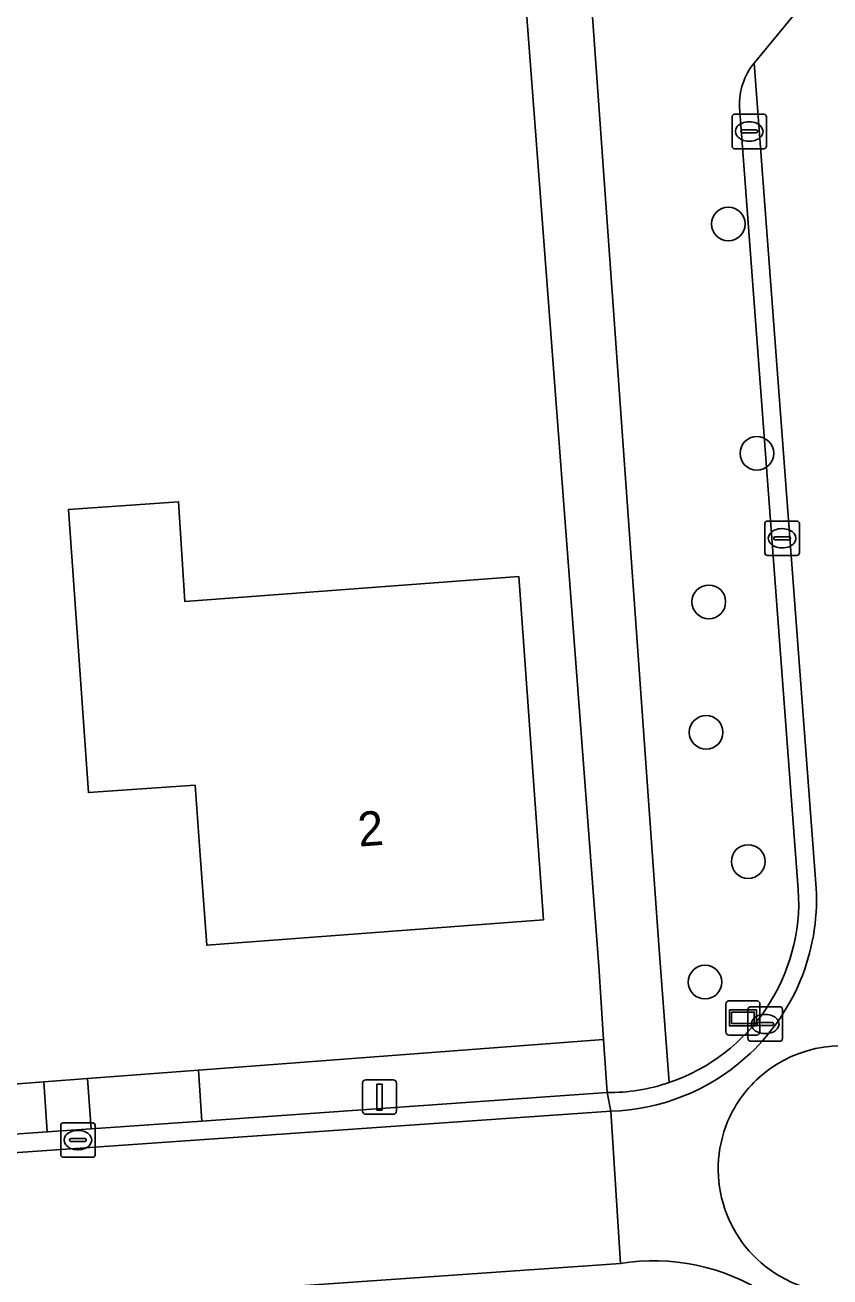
# Model space of a CAD drawing. Extents: x 162661 to 163484, y 380247 to 381230.
# Drawn here: x 163109.5 to 163132.86, y 380399.85 to 380436.19 of the extents above; entities that cross this region are included whole.
import ezdxf

# ---------------------------------------------------------------- set-up
doc = ezdxf.new("R2010")
doc.units = 0
for name, color, linetype in [('IMGEO_Boom', 7, 'Continuous'), ('IMGEO_Erf', 7, 'Continuous'), ('IMGEO_Groenvoorziening', 7, 'Continuous'), ('IMGEO_Kolk', 7, 'Continuous'), ('IMGEO_Lichtmast', 7, 'Continuous'), ('IMGEO_Pand', 7, 'Continuous'), ('IMGEO_Pand_nummerreeks', 7, 'Continuous'), ('IMGEO_Rijbaan_lokaal_gesloten', 7, 'Continuous'), ('IMGEO_Rijbaan_lokaal_open', 7, 'Continuous'), ('IMGEO_Straatnaambord', 7, 'Continuous'), ('IMGEO_Voetpad_open', 7, 'Continuous')]:
    doc.layers.add(name, color=color, linetype=linetype)

msp = doc.modelspace()

# ---------------------------------------------------------------- linework, layer by layer
at = {"layer": 'IMGEO_Boom'}
for centre in [(163129.913, 380430.416), (163130.742, 380423.759), (163129.347, 380419.447), (163129.269, 380415.66), (163130.49, 380411.91), (163129.236, 380408.411)]:
    msp.add_circle(centre, 0.489, dxfattribs=at)
at = {"layer": 'IMGEO_Erf'}
msp.add_lwpolyline([(163059.202, 380401.669), (163072.831, 380402.7), (163076.355, 380402.967), (163083.412, 380403.501), (163085.079, 380403.627), (163089.515, 380403.963), (163093.438, 380404.26), (163106.644, 380405.259), (163110.041, 380405.516), (163111.313, 380405.612), (163114.53, 380405.856), (163126.293, 380406.746), (163126.155, 380408.871), (163123.094, 380449.195)], dxfattribs=at)
msp.add_lwpolyline([(163110.764, 380422.13), (163113.956, 380422.354), (163114.136, 380419.459), (163123.829, 380420.187), (163124.544, 380410.218), (163114.776, 380409.483), (163114.583, 380412.095), (163114.433, 380414.127), (163111.341, 380413.91)], close=True, dxfattribs=at)
at = {"layer": 'IMGEO_Groenvoorziening'}
for points in [[(163129.483, 380443.709), (163128.717, 380454.219), (163128.599, 380455.668), (163127.675, 380455.574), (163127.354, 380455.539), (163124.446, 380455.354), (163125.156, 380447.82), (163127.91, 380409.357), (163128.192, 380405.494)], [(163130.659, 380435.085), (163132.068, 380436.79)], [(163131.945, 380411.096), (163130.236, 380433.81)]]:
    msp.add_lwpolyline(points, dxfattribs=at)
for points in [[(163126.293, 380406.746), (163114.53, 380405.856), (163114.634, 380404.378), (163126.393, 380405.204)], [(163111.313, 380405.612), (163110.041, 380405.516), (163110.143, 380404.063), (163111.415, 380404.152)]]:
    msp.add_lwpolyline(points, close=True, dxfattribs=at)
for centre, radius, start, end in [((163132.167, 380433.877), 1.932, 141.3069, 181.9851), ((163126.42, 380410.739), 5.536, 288.6626, 3.698)]:
    msp.add_arc(centre, radius, start, end, dxfattribs=at)
at = {"layer": 'IMGEO_Kolk'}
for p, q in [((163130.02, 380432.675), (163130.02, 380433.527)), ((163130.095, 380433.601), (163130.947, 380433.601)), ((163130.508, 380433.381), (163130.533, 380433.381)), ((163131.021, 380433.527), (163131.021, 380432.675)), ((163130.279, 380433.095), (163130.279, 380433.107)), ((163130.717, 380433.058), (163130.319, 380433.058)), ((163130.322, 380433.144), (163130.72, 380433.144)), ((163130.763, 380433.107), (163130.763, 380433.095)), ((163130.947, 380432.601), (163130.095, 380432.601)), ((163130.531, 380432.821), (163130.506, 380432.821)), ((163130.974, 380420.867), (163130.974, 380421.719)), ((163131.049, 380421.793), (163131.901, 380421.793)), ((163131.975, 380421.719), (163131.975, 380420.867)), ((163131.276, 380421.336), (163131.674, 380421.336)), ((163131.462, 380421.573), (163131.487, 380421.573)), ((163131.233, 380421.287), (163131.233, 380421.299)), ((163131.671, 380421.25), (163131.273, 380421.25)), ((163131.485, 380421.013), (163131.46, 380421.013)), ((163131.717, 380421.299), (163131.717, 380421.287)), ((163131.901, 380420.793), (163131.049, 380420.793)), ((163130.484, 380406.769), (163130.484, 380407.621)), ((163130.559, 380407.695), (163131.411, 380407.695)), ((163131.485, 380407.621), (163131.485, 380406.769)), ((163130.743, 380407.189), (163130.743, 380407.201)), ((163130.786, 380407.238), (163131.184, 380407.238)), ((163130.972, 380407.475), (163130.997, 380407.475)), ((163131.227, 380407.201), (163131.227, 380407.189)), ((163131.181, 380407.152), (163130.783, 380407.152)), ((163130.995, 380406.915), (163130.97, 380406.915)), ((163131.411, 380406.695), (163130.559, 380406.695)), ((163110.534, 380403.4), (163110.534, 380404.252)), ((163110.609, 380404.326), (163111.461, 380404.326)), ((163111.535, 380404.252), (163111.535, 380403.4)), ((163111.022, 380404.106), (163111.047, 380404.106)), ((163110.793, 380403.82), (163110.793, 380403.832)), ((163111.231, 380403.783), (163110.833, 380403.783)), ((163110.836, 380403.869), (163111.234, 380403.869)), ((163111.045, 380403.546), (163111.02, 380403.546)), ((163111.277, 380403.832), (163111.277, 380403.82)), ((163111.461, 380403.326), (163110.609, 380403.326))]:
    msp.add_line(p, q, dxfattribs=at)
for points in [[(163130.02, 380432.675), (163130.02, 380433.527)], [(163130.095, 380433.601), (163130.947, 380433.601)], [(163131.021, 380433.527), (163131.021, 380432.675)], [(163130.947, 380432.601), (163130.095, 380432.601)], [(163130.974, 380420.867), (163130.974, 380421.719)], [(163131.049, 380421.793), (163131.901, 380421.793)], [(163131.975, 380421.719), (163131.975, 380420.867)], [(163131.901, 380420.793), (163131.049, 380420.793)], [(163130.484, 380406.769), (163130.484, 380407.621)], [(163130.559, 380407.695), (163131.411, 380407.695)], [(163131.485, 380407.621), (163131.485, 380406.769)], [(163131.411, 380406.695), (163130.559, 380406.695)], [(163110.534, 380403.4), (163110.534, 380404.252)], [(163110.609, 380404.326), (163111.461, 380404.326)], [(163111.535, 380404.252), (163111.535, 380403.4)], [(163111.461, 380403.326), (163110.609, 380403.326)]]:
    msp.add_lwpolyline(points, dxfattribs=at)
for centre, radius, start, end in [((163130.097, 380433.525), 0.0765, 91.552, 178.448), ((163130.097, 380433.525), 0.0765, 91.552, 178.448), ((163130.945, 380433.525), 0.0765, 1.552, 88.448), ((163130.945, 380433.525), 0.0765, 1.552, 88.448), ((163130.319, 380433.104), 0.0403, 85.8775, 175.7526), ((163130.316, 380433.094), 0.0366, 178.938, 274.7102), ((163130.72, 380433.101), 0.043, 264.8664, 352.4533), ((163130.724, 380433.106), 0.0386, 1.7309, 96.639), ((163130.097, 380432.677), 0.0765, 181.552, 268.448), ((163130.097, 380432.677), 0.0765, 181.552, 268.448), ((163130.945, 380432.677), 0.0765, 271.552, 358.448), ((163130.945, 380432.677), 0.0765, 271.552, 358.448), ((163131.051, 380421.717), 0.0765, 91.552, 178.448), ((163131.051, 380421.717), 0.0765, 91.552, 178.448), ((163131.899, 380421.717), 0.0765, 1.552, 88.448), ((163131.899, 380421.717), 0.0765, 1.552, 88.448), ((163131.273, 380421.296), 0.0403, 85.8775, 175.7526), ((163131.678, 380421.298), 0.0386, 1.7309, 96.639), ((163131.27, 380421.286), 0.0366, 178.938, 274.7102), ((163131.674, 380421.293), 0.043, 264.8664, 352.4533), ((163131.051, 380420.869), 0.0765, 181.552, 268.448), ((163131.051, 380420.869), 0.0765, 181.552, 268.448), ((163131.899, 380420.869), 0.0765, 271.552, 358.448), ((163131.899, 380420.869), 0.0765, 271.552, 358.448), ((163130.561, 380407.619), 0.0765, 91.552, 178.448), ((163130.561, 380407.619), 0.0765, 91.552, 178.448), ((163131.409, 380407.619), 0.0765, 1.552, 88.448), ((163131.409, 380407.619), 0.0765, 1.552, 88.448), ((163130.783, 380407.198), 0.0403, 85.8775, 175.7526), ((163130.78, 380407.188), 0.0366, 178.938, 274.7102), ((163131.184, 380407.195), 0.043, 264.8664, 352.4533), ((163131.188, 380407.2), 0.0386, 1.7309, 96.639), ((163130.561, 380406.771), 0.0765, 181.552, 268.448), ((163130.561, 380406.771), 0.0765, 181.552, 268.448), ((163131.409, 380406.771), 0.0765, 271.552, 358.448), ((163131.409, 380406.771), 0.0765, 271.552, 358.448), ((163110.611, 380404.25), 0.0765, 91.552, 178.448), ((163110.611, 380404.25), 0.0765, 91.552, 178.448), ((163111.459, 380404.25), 0.0765, 1.552, 88.448), ((163111.459, 380404.25), 0.0765, 1.552, 88.448), ((163110.833, 380403.829), 0.0403, 85.8775, 175.7526), ((163110.83, 380403.819), 0.0366, 178.938, 274.7102), ((163111.234, 380403.826), 0.043, 264.8664, 352.4533), ((163111.238, 380403.831), 0.0386, 1.7309, 96.639), ((163110.611, 380403.402), 0.0765, 181.552, 268.448), ((163110.611, 380403.402), 0.0765, 181.552, 268.448), ((163111.459, 380403.402), 0.0765, 271.552, 358.448), ((163111.459, 380403.402), 0.0765, 271.552, 358.448)]:
    msp.add_arc(centre, radius, start, end, dxfattribs=at)
for centre, major_axis, ratio, start_param, end_param in [((163130.507, 380433.101), (-0.387, 0.002), 0.722429, 4.712389, 7.853982), ((163130.532, 380433.101), (-0.39, 0.002), 0.717154, 1.570796, 4.712389), ((163131.461, 380421.293), (-0.387, 0.002), 0.722429, 4.712389, 7.853982), ((163131.486, 380421.293), (-0.39, 0.002), 0.717154, 1.570796, 4.712389), ((163130.971, 380407.195), (-0.387, 0.002), 0.722429, 4.712389, 7.853982), ((163130.996, 380407.195), (-0.39, 0.002), 0.717154, 1.570796, 4.712389), ((163111.021, 380403.826), (-0.387, 0.002), 0.722429, 4.712389, 7.853982), ((163111.046, 380403.826), (-0.39, 0.002), 0.717154, 1.570796, 4.712389)]:
    msp.add_ellipse(centre, major_axis=major_axis, ratio=ratio, start_param=start_param, end_param=end_param, dxfattribs=at)
at = {"layer": 'IMGEO_Lichtmast'}
for p, q in [((163119.293, 380404.673), (163119.293, 380405.473)), ((163119.293, 380405.473), (163119.293, 380404.673)), ((163119.393, 380405.573), (163120.183, 380405.573)), ((163120.183, 380405.573), (163119.393, 380405.573)), ((163120.283, 380405.473), (163120.283, 380404.673)), ((163120.283, 380404.673), (163120.283, 380405.473)), ((163120.183, 380404.573), (163119.393, 380404.573)), ((163119.393, 380404.573), (163120.183, 380404.573))]:
    msp.add_line(p, q, dxfattribs=at)
msp.add_lwpolyline([(163119.713, 380405.448), (163119.863, 380405.448), (163119.863, 380404.698), (163119.713, 380404.698), (163119.713, 380405.448)], dxfattribs=at)
for centre, start, end in [((163119.393, 380405.473), 90, 180), ((163119.393, 380405.473), 90, 180), ((163120.183, 380405.473), 0, 90), ((163120.183, 380405.473), 360, 90), ((163119.393, 380404.673), 180, 270), ((163119.393, 380404.673), 180, 270), ((163120.183, 380404.673), 270, 0), ((163120.183, 380404.673), 270, 0)]:
    msp.add_arc(centre, 0.1, start, end, dxfattribs=at)
at = {"layer": 'IMGEO_Pand'}
msp.add_lwpolyline([(163111.341, 380413.91), (163114.433, 380414.127), (163114.583, 380412.095), (163114.776, 380409.483), (163124.544, 380410.218), (163123.829, 380420.187), (163114.136, 380419.459), (163113.956, 380422.354), (163110.764, 380422.13)], close=True, dxfattribs=at)
at = {"layer": 'IMGEO_Rijbaan_lokaal_gesloten'}
for points in [[(163132.068, 380436.79), (163130.659, 380435.085), (163132.464, 380411.134)], [(163126.503, 380404.662), (163062.407, 380400.199)], [(163064.883, 380395.926), (163126.779, 380400.24), (163126.503, 380404.662)], [(163126.503, 380404.662), (163126.779, 380400.24)]]:
    msp.add_lwpolyline(points, dxfattribs=at)
for centre, radius, start, end in [((163126.323, 380410.81), 6.149, 311.713, 3.0175), ((163133.212, 380402.964), 3.601, 2.865, 130.302), ((163126.318, 380410.816), 6.156, 271.7174, 311.7136), ((163133.207, 380402.967), 3.595, 130.2765, 156.7899), ((163133.223, 380402.987), 3.602, 157.1843, 239.7923), ((163133.224, 380402.985), 3.601, 239.7745, 328.8373), ((163127.761, 380394.35), 5.972, 56.8255, 99.4679)]:
    msp.add_arc(centre, radius, start, end, dxfattribs=at)
at = {"layer": 'IMGEO_Rijbaan_lokaal_open'}
for points in [[(163132.464, 380411.134), (163130.659, 380435.085)], [(163130.236, 380433.81), (163131.945, 380411.096)], [(163126.503, 380404.662), (163126.393, 380405.204), (163114.634, 380404.378), (163111.415, 380404.152), (163110.143, 380404.063), (163106.745, 380403.824), (163093.564, 380402.898), (163089.584, 380402.619), (163085.196, 380402.311), (163083.53, 380402.194), (163076.444, 380401.696), (163072.919, 380401.448), (163062.309, 380400.703)], [(163126.393, 380405.204), (163126.503, 380404.662)], [(163062.407, 380400.199), (163126.503, 380404.662)], [(163126.779, 380400.24), (163064.883, 380395.926)]]:
    msp.add_lwpolyline(points, dxfattribs=at)
for centre, radius, start, end in [((163132.167, 380433.877), 1.932, 141.3069, 181.9851), ((163126.42, 380410.739), 5.536, 288.6626, 3.698), ((163126.323, 380410.81), 6.149, 311.713, 3.0175), ((163133.212, 380402.964), 3.601, 2.865, 130.302), ((163126.318, 380410.816), 6.156, 271.7174, 311.7136), ((163133.207, 380402.967), 3.595, 130.2765, 156.7899), ((163126.43, 380410.701), 5.497, 269.6166, 288.698), ((163133.223, 380402.987), 3.602, 157.1843, 239.7923), ((163133.224, 380402.985), 3.601, 239.7745, 328.8373), ((163127.761, 380394.35), 5.972, 56.8255, 99.4679)]:
    msp.add_arc(centre, radius, start, end, dxfattribs=at)
at = {"layer": 'IMGEO_Straatnaambord'}
for p, q in [((163129.842, 380406.972), (163129.842, 380407.772)), ((163129.842, 380407.772), (163129.842, 380406.972)), ((163129.942, 380407.872), (163130.732, 380407.872)), ((163130.732, 380407.872), (163129.942, 380407.872)), ((163130.832, 380407.772), (163130.832, 380406.972)), ((163130.832, 380406.972), (163130.832, 380407.772)), ((163130.732, 380406.872), (163129.942, 380406.872)), ((163129.942, 380406.872), (163130.732, 380406.872))]:
    msp.add_line(p, q, dxfattribs=at)
for points in [[(163129.943, 380407.604), (163130.731, 380407.604), (163130.731, 380407.14), (163129.943, 380407.14), (163129.943, 380407.604)], [(163130.008, 380407.539), (163130.008, 380407.205), (163130.666, 380407.205), (163130.666, 380407.539), (163130.008, 380407.539)]]:
    msp.add_lwpolyline(points, dxfattribs=at)
for centre, start, end in [((163129.942, 380407.772), 90, 180), ((163129.942, 380407.772), 90, 180), ((163130.732, 380407.772), 0, 90), ((163130.732, 380407.772), 360, 90), ((163129.942, 380406.972), 180, 270), ((163129.942, 380406.972), 180, 270), ((163130.732, 380406.972), 270, 0), ((163130.732, 380406.972), 270, 0)]:
    msp.add_arc(centre, 0.1, start, end, dxfattribs=at)
at = {"layer": 'IMGEO_Voetpad_open'}
for points in [[(163125.156, 380447.82), (163124.446, 380455.354), (163122.658, 380455.201), (163123.094, 380449.195), (163126.155, 380408.871), (163126.293, 380406.746), (163126.393, 380405.204)], [(163128.192, 380405.494), (163127.91, 380409.357), (163125.156, 380447.82)]]:
    msp.add_lwpolyline(points, dxfattribs=at)
for points in [[(163114.53, 380405.856), (163111.313, 380405.612), (163111.415, 380404.152), (163114.634, 380404.378)], [(163110.041, 380405.516), (163106.644, 380405.259), (163106.745, 380403.824), (163110.143, 380404.063)]]:
    msp.add_lwpolyline(points, close=True, dxfattribs=at)
msp.add_arc((163126.43, 380410.701), 5.497, 269.6166, 288.698, dxfattribs=at)

# ---------------------------------------------------------------- texts
at = {"layer": 'IMGEO_Pand_nummerreeks'}
msp.add_text('2', height=1, rotation=4.3032, dxfattribs=at).set_placement((163119.194, 380412.342))

doc.saveas('drawing.dxf')
